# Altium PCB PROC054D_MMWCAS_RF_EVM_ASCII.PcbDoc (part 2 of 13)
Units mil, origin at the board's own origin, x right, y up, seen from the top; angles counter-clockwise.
Board outline 6299.21 x 5370.07 mil, 8 copper layers (L1 TOP, L2 GND, L3 SIGNAL 1, L4 GND, L5 SIGNAL 2, L6 SIGNAL 3, L7 GND, L8 BOTTOM), stack 53.5 mil thick; 775 components, 552 nets, 2648 pads, 7845 vias.
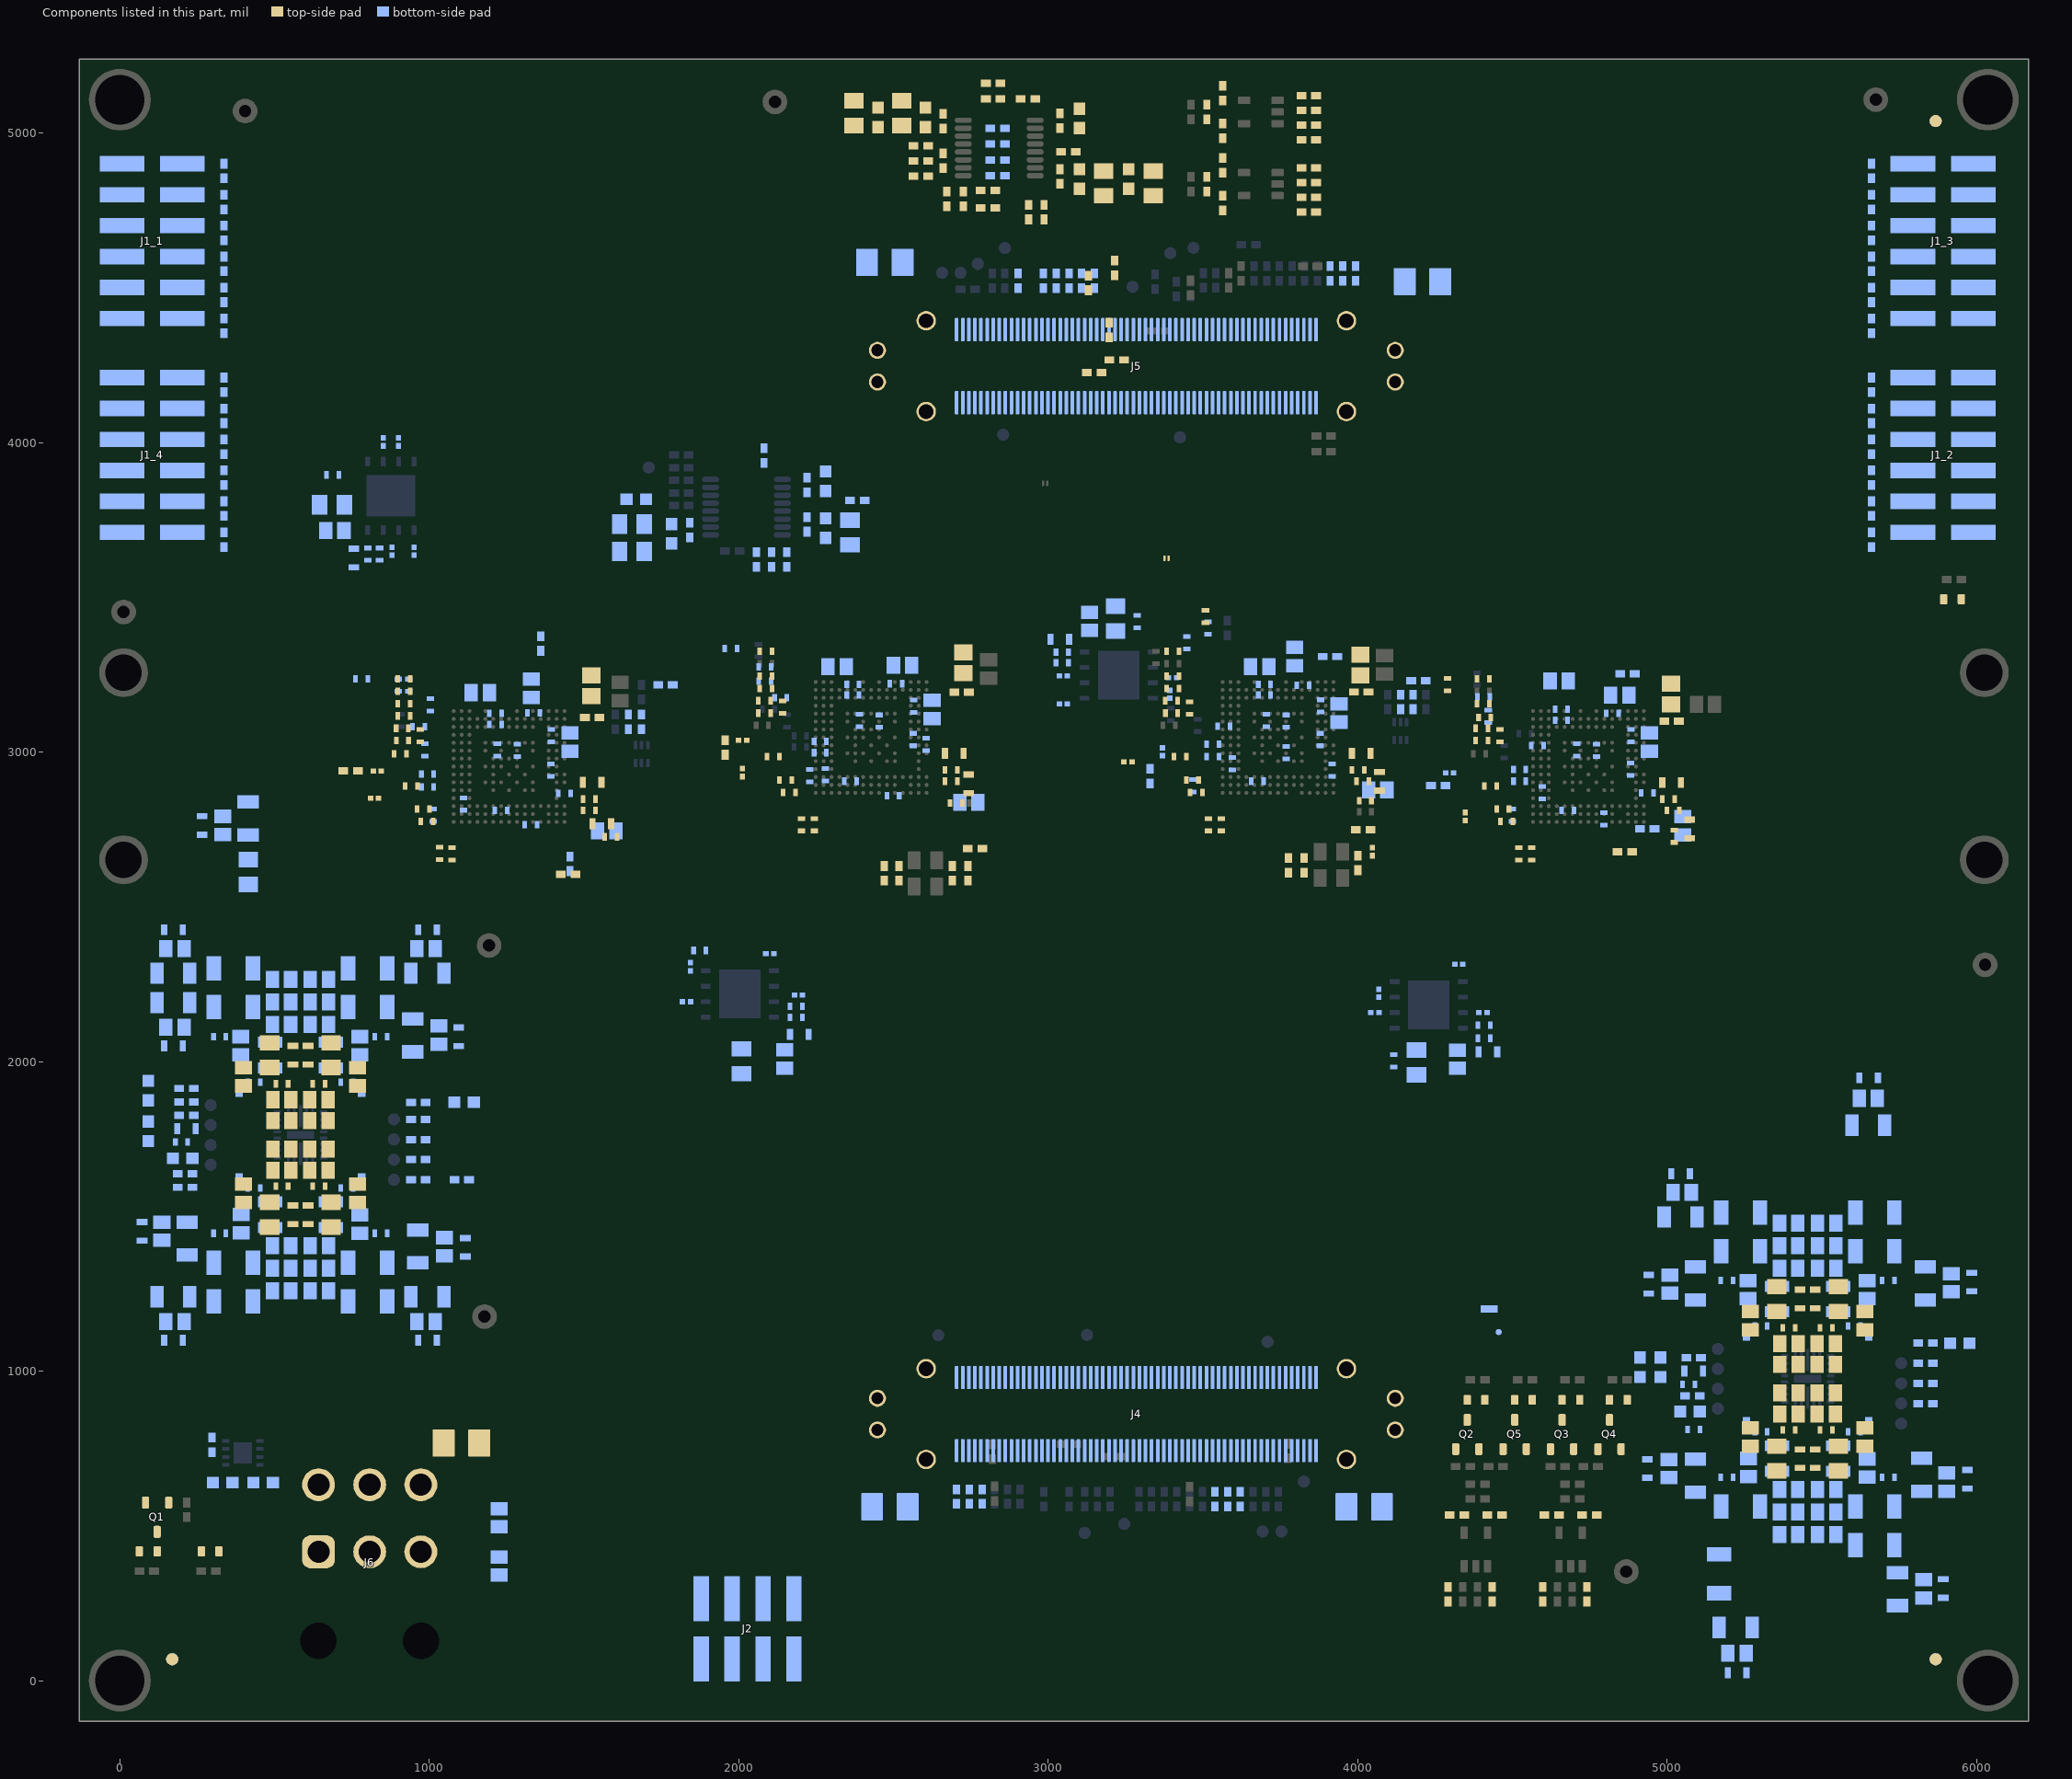
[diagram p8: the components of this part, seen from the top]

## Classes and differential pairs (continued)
net class "LC Power": AWR_1_1V0_RF1_FILT AWR_1_1V0_RF2_FILT AWR_1_1V2_FILT AWR_1_1V8_FILT AWR_2_1V0_RF1_FILT AWR_2_1V0_RF2_FILT AWR_2_1V2_FILT AWR_2_1V8_FILT AWR_3_1V0_RF1_FILT AWR_3_1V0_RF2_FILT AWR_3_1V2_FILT AWR_3_1V8_FILT AWR_4_1V0_RF1_FILT AWR_4_1V0_RF2_FILT AWR_4_1V2_FILT AWR_4_1V8_FILT
net class AWR_SYNC: AWR_1_DIG_SYNCIN AWR_1_DIG_SYNCIN_RS AWR_1_DIG_SYNCOUT AWR_2_DIG_SYNCIN AWR_2_DIG_SYNCIN_RS AWR_2_DIG_SYNCOUT AWR_3_DIG_SYNCIN AWR_3_DIG_SYNCIN_RS AWR_3_DIG_SYNCOUT AWR_4_DIG_SYNCIN AWR_4_DIG_SYNCIN_RS AWR_4_DIG_SYNCOUT DIG_SYNC_SOURCE DIG_SYNCOUT_RS_1 DIG_SYNCOUT_RS_2 DIG_SYNCOUT_RS_3 DIG_SYNCOUT_RS_4 EXT_DIG_SYNC
net class AWR_CLOCK: 40M_BUF_IN_PRIMAWRY 40M_BUF_IN_SECONDAWRY AWR_1_MCU_CLKOUT AWR_1_MCU_CLKOUT_CONN AWR_1_MCU_CLKOUT_RS AWR_1_OSC_CLKOUT AWR_1_OSC_CLKOUT_CONN AWR_1_PMIC_CLKOUT AWR_1_XTAL_CLKM AWR_1_XTAL_CLKP AWR_1_XTALP_RS AWR_2_MCU_CLKOUT AWR_2_OSC_CLKOUT AWR_2_PMIC_CLKOUT AWR_2_XTAL_CLKM AWR_2_XTAL_CLKP AWR_3_MCU_CLKOUT AWR_3_OSC_CLKOUT AWR_3_OSC_CLKOUT_CONN AWR_3_PMIC_CLKOUT AWR_3_XTAL_CLKM AWR_3_XTAL_CLKP AWR_3_XTALP_RS AWR_4_MCU_CLKOUT AWR_4_OSC_CLKOUT AWR_4_PMIC_CLKOUT AWR_4_XTAL_CLKM AWR_4_XTAL_CLKP BUF_CLKOUT1 BUF_CLKOUT1_RS BUF_CLKOUT2_RS BUF_CLKOUT3 BUF_CLKOUT3_RS BUF_CLKOUT4_RS EXT_40M_BUF_AWR_1_RS EXT_40MHZ_CLK_1V8 MCU_CLKOUT_RS_1 MCU_CLKOUT_RS_2 MCU_CLKOUT_RS_3 MCU_CLKOUT_RS_4 OSC_CLKOUT_RS_1 OSC_CLKOUT_RS_2 OSC_CLKOUT_RS_3 OSC_CLKOUT_RS_4 PMIC_CLKOUT_RS_1 PMIC_CLKOUT_RS_2 PMIC_CLKOUT_RS_3 PMIC_CLKOUT_RS_4
net class AWR_FMCW_20G: AWR_1_FMCW_CLKOUT AWR_1_FMCW_SYNCOUT AWR_2_FMCW_CLKOUT AWR_2_FMCW_SYNCOUT AWR_3_FMCW_CLKOUT AWR_3_FMCW_SYNCOUT AWR_4_FMCW_CLKOUT AWR_4_FMCW_SYNCOUT
net class 12XX_GENERAL: AWR_1_SPI_CLK1 AWR_1_SPI_CS1 AWR_1_SPI_HOST_INTR1 AWR_1_SPI_MISO1 AWR_1_SPI_MOSI1 AWR_2_SPI_CLK1 AWR_2_SPI_CS1 AWR_2_SPI_HOST_INTR1 AWR_2_SPI_MISO1 AWR_2_SPI_MOSI1 AWR_3_SPI_CLK1 AWR_3_SPI_CS1 AWR_3_SPI_HOST_INTR1 AWR_3_SPI_MISO1 AWR_3_SPI_MOSI1 AWR_4_SPI_CLK1 AWR_4_SPI_CS1 AWR_4_SPI_HOST_INTR1 AWR_4_SPI_MISO1 AWR_4_SPI_MOSI1 SPI_HOST_INTR1_RS_1 SPI_HOST_INTR1_RS_2 SPI_HOST_INTR1_RS_3 SPI_HOST_INTR1_RS_4 SPI_MISO1_RS_1 SPI_MISO1_RS_2 SPI_MISO1_RS_3 SPI_MISO1_RS_4
net class AWR_JTAG: AWR_1_TCK AWR_1_TDI AWR_1_TDO AWR_1_TMS AWR_2_TCK AWR_2_TDI AWR_2_TDO AWR_2_TMS AWR_3_TCK AWR_3_TDI AWR_3_TDO AWR_3_TMS AWR_4_TCK AWR_4_TDI AWR_4_TDO AWR_4_TMS TDO_RS_1 TDO_RS_2 TDO_RS_3 TDO_RS_4
net class "Back Drill Nets": AWR_1_FMCW_CLKOUT AWR_1_FMCW_SYNCOUT AWR_3_FMCW_CLKOUT
component class AWR_4: R174_4 R175_4 R176_4 R177_4 R178_4 R179_4 R180_4 R181_4 R182_4 R183_4 R184_4 R185_4
differential pair 12XX_4_LVDS_VALID: +AWR_4_LVDS_VALID_P -AWR_4_LVDS_VALID_N
differential pair 12XX_4_LVDS_FRCLK: +AWR_4_LVDS_FRCLK_P -AWR_4_LVDS_FRCLK_N
differential pair 12XX_4_CSI2_TX3: +AWR_4_CSI2_TX3_P -AWR_4_CSI2_TX3_N
differential pair 12XX_4_CSI2_TX2: +AWR_4_CSI2_TX2_P -AWR_4_CSI2_TX2_N
differential pair 12XX_4_CSI2_TX1: +AWR_4_CSI2_TX1_P -AWR_4_CSI2_TX1_N
differential pair 12XX_4_CSI2_TX0: +AWR_4_CSI2_TX0_P -AWR_4_CSI2_TX0_N
differential pair 12XX_4_CSI2_CLK: +AWR_4_CSI2_CLK_P -AWR_4_CSI2_CLK_N
differential pair 12XX_3_LVDS_VALID: +AWR_3_LVDS_VALID_P -AWR_3_LVDS_VALID_N
differential pair 12XX_3_LVDS_FRCLK: +AWR_3_LVDS_FRCLK_P -AWR_3_LVDS_FRCLK_N
differential pair 12XX_3_CSI2_TX3: +AWR_3_CSI2_TX3_P -AWR_3_CSI2_TX3_N
differential pair 12XX_3_CSI2_TX2: +AWR_3_CSI2_TX2_P -AWR_3_CSI2_TX2_N
differential pair 12XX_3_CSI2_TX1: +AWR_3_CSI2_TX1_P -AWR_3_CSI2_TX1_N
differential pair 12XX_3_CSI2_TX0: +AWR_3_CSI2_TX0_P -AWR_3_CSI2_TX0_N
differential pair 12XX_3_CSI2_CLK: +AWR_3_CSI2_CLK_P -AWR_3_CSI2_CLK_N
differential pair 12XX_2_LVDS_VALID: +AWR_2_LVDS_VALID_P -AWR_2_LVDS_VALID_N
differential pair 12XX_2_LVDS_FRCLK: +AWR_2_LVDS_FRCLK_P -AWR_2_LVDS_FRCLK_N
differential pair 12XX_2_CSI2_TX3: +AWR_2_CSI2_TX3_P -AWR_2_CSI2_TX3_N
differential pair 12XX_2_CSI2_TX2: +AWR_2_CSI2_TX2_P -AWR_2_CSI2_TX2_N
differential pair 12XX_2_CSI2_TX1: +AWR_2_CSI2_TX1_P -AWR_2_CSI2_TX1_N
differential pair 12XX_2_CSI2_TX0: +AWR_2_CSI2_TX0_P -AWR_2_CSI2_TX0_N
differential pair 12XX_2_CSI2_CLK: +AWR_2_CSI2_CLK_P -AWR_2_CSI2_CLK_N
differential pair 12XX_1_LVDS_VALID: +AWR_1_LVDS_VALID_P -AWR_1_LVDS_VALID_N
differential pair 12XX_1_LVDS_FRCLK: +AWR_1_LVDS_FRCLK_P -AWR_1_LVDS_FRCLK_N
differential pair 12XX_1_CSI2_TX3: +AWR_1_CSI2_TX3_P -AWR_1_CSI2_TX3_N
differential pair 12XX_1_CSI2_TX2: +AWR_1_CSI2_TX2_P -AWR_1_CSI2_TX2_N
differential pair 12XX_1_CSI2_TX1: +AWR_1_CSI2_TX1_P -AWR_1_CSI2_TX1_N
differential pair 12XX_1_CSI2_TX0: +AWR_1_CSI2_TX0_P -AWR_1_CSI2_TX0_N
differential pair " ": +AWR_1_CSI2_CLK_P -AWR_1_CSI2_CLK_N

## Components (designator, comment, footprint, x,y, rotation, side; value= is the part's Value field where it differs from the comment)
C1_1 "GCM188R71C105KA64D" 0603S 2742.78,2897.55 r90 top locked (schematic designator C1)
C1_2 "GCM188R71C105KA64D" 0603S 5073.3,2751.83 r270 top locked (schematic designator C1)
C1_3 "GCM188R71C105KA64D" 0603S 4070.8,2905.83 r90 top locked (schematic designator C1)
C1_4 "GCM188R71C105KA64D" 0603S 1557.76,2768.38 r0 top locked (schematic designator C1)
C2_1 "GCM155R71C224KE02D" 0402S 2563.59,3040.51 r90 bottom locked (schematic designator C2)
C2_2 "GCM155R71C224KE02D" 0402S 4881.59,2945.09 r90 bottom locked (schematic designator C2)
C2_3 "GCM155R71C224KE02D" 0402S 3878.59,3040.51 r90 bottom locked (schematic designator C2)
C2_4 "GCM155R71C224KE02D" 0402S 1393,2941.71 r90 bottom locked (schematic designator C2)
C3_1 "GCM188R71C105KA64D" 0603S 2696.55,2995.81 r0 top locked (schematic designator C3)
C3_2 "GCM188R71C105KA64D" 0603S 5014.55,2901.32 r0 top locked (schematic designator C3)
C3_3 "GCM188R71C105KA64D" 0603S 4011.55,2995.81 r0 top locked (schematic designator C3)
C3_4 "GCM188R71C105KA64D" 0603S 1526.55,2902.31 r0 top locked (schematic designator C3)
C4_1 "GCM155R71C224KE02D" 0402 2720.13,3194 r0 top locked (schematic designator C4)
C4_2 "GCM155R71C224KE02D" 0402 5014.43,3100.3 r0 top locked (schematic designator C4)
C4_3 "GCM155R71C224KE02D" 0402 4011.43,3194.3 r0 top locked (schematic designator C4)
C4_4 "GCM155R71C224KE02D" 0402 1526.43,3112.3 r0 top locked (schematic designator C4)
C5_1 "GCM21BR71A106KE22L" 0805 2725.58,3288.52 r90 top locked (schematic designator C5)
C5_2 "GCM21BR71A106KE22L" 0805 5012.4,3187.53 r90 top locked (schematic designator C5)
C5_3 "GCM21BR71A106KE22L" 0805 4008.9,3281.53 r90 top locked (schematic designator C5)
C5_4 "GCM21BR71A106KE22L" 0805 1523.9,3214.53 r90 top locked (schematic designator C5)
C6_1 "GCM21BR71A106KE22L" 0805L 2148.35,2008.07 r270 bottom locked (schematic designator C6)
C6_2 "GCM21BR71A106KE22L" 0805L 4322.67,2007.69 r270 bottom locked (schematic designator C6)
C6_3 "GCM21BR71A106KE22L" 0805L 3133.93,3422.47 r90 bottom locked (schematic designator C6)
C6_4 "GCM21BR71A106KE22L" 0805L 694.69,3715.83 r180 bottom locked (schematic designator C6)
C7_1 "GCM188R71C105KA64D" 0603S 2195.91,2087.69 r0 bottom locked (schematic designator C7)
C7_2 "GCM188R71C105KA64D" 0603S 4421.14,2031.28 r0 bottom locked (schematic designator C7)
C7_3 "GCM188R71C105KA64D" 0603S 3037.86,3364.87 r180 bottom locked (schematic designator C7)
C7_4 "GCM188R71C105KA64D" 0603S 756.26,3626.9 r270 bottom locked (schematic designator C7)
C8_1 "CGA2B3X7R1H104K050BB" 0402S 2185.91,2143.45 r0 bottom locked (schematic designator C8)
C8_2 "CGA2B3X7R1H104K050BB" 0402S 4408.64,2075.26 r0 bottom locked (schematic designator C8)
C8_3 "CGA2B3X7R1H104K050BB" 0402S 3045.36,3323.4 r180 bottom locked (schematic designator C8)
C8_4 "CGA2B3X7R1H104K050BB" 0402S 802,3639.4 r270 bottom locked (schematic designator C8)
C9 "GCM155R71C104KA55D" 0402 297.71,761.49 r90 bottom locked
C10 "GCM21BR71A106KE22L" 0805L 522.33,1259.8 r0 bottom locked
C11 "GCM31CR71A226KE02" 1206_180L 173.03,1240.08 r180 bottom locked
C12 "GCM21BR71A106KE22L" 0805L 178.04,1160.14 r180 bottom locked
C13 "GCM188R71C105KA64J" 0603S 173.04,1099.98 r180 bottom locked
C14 "GCM21BR71A106KE22L" 0805L 522.33,2193.13 r0 bottom locked
C15 "GCM31CR71A226KE02" 1206_180L 173.03,2190.59 r180 bottom locked
C16 "GCM21BR71A106KE22L" 0805L 178.04,2110.65 r180 bottom locked
C17 "GCM188R71C105KA64J" 0603S 173.04,2050.48 r180 bottom locked
C18 "GCM31CR71A226KE02" 1206_180L 414.55,2785.62 r90 bottom locked
C19 "GCM21BR71A106KE22L" 0805L 332.11,2762.78 r90 bottom locked
C20 "GCM188R71C105KA64J" 0603S 265.9,2763.05 r90 bottom locked
C21 "GCM31CR71A226KE02" 1206_180L 217.55,1428.37 r90 bottom locked
C22 "GCM31CR71A226KE02" 1206_180L 962.95,1403.1 r90 bottom locked
C23 "GCM21BR71A106KE22L" 0805L 1049.07,1401.66 r90 bottom locked
C24 "GCM31CR71A226KE02" 1206_180L 994.04,1240.08 r0 bottom locked
C25 "GCM21BR71A106KE22L" 0805L 644.75,1332.8 r180 bottom locked
C26 "GCM188R71C105KA64J" 0603S 1116.49,1399.97 r90 bottom locked
C27 "GCM21BR71A106KE22L" 0805L 644.75,1259.8 r180 bottom locked
C28 "GCM188R71C105KA64J" 0603S 994.03,1099.98 r0 bottom locked
C29 "GCM21BR71A106KE22L" 0805L 135.75,1452 r90 bottom locked
C30 "GCM31CR71A226KE02" 1206_180L 994.04,2285.85 r0 bottom locked
C31 "GCM21BR71A106KE22L" 0805L 989.03,2365.79 r0 bottom locked
C32 "GCM21BR71A106KE22L" 0805L 989.03,1160.14 r0 bottom locked
C33 "GCM21BR71A106KE22L" 0805L 644.75,2266.12 r180 bottom locked
C34 "GCM188R71C105KA64J" 0603S 994.03,2425.95 r0 bottom locked
C35 "GCM21BR71A106KE22L" 0805L 644.75,2193.13 r180 bottom locked
C36 "GCM188R71C105KA64J" 0603S 1095.23,2080.31 r270 bottom locked
C37 "GCM155R71H391KA37D" 0402S 733.8,1591.98 r0 bottom locked
C38 "GCM155R71H391KA37D" 0402S 433.28,1591.98 r180 bottom locked
C39 "GCM188R72A682KA37D" 0603S 608.24,1505.01 r90 top locked
C40 "GRM21BR60J107M" 0805L 643.44,1716.98 r180 top locked
C41 "GRM21BR60J107M" 0805L 768.09,1574.81 r90 top locked
C42 "GCM155R71C104JA55D" 0402S 643.45,1597.62 r180 top locked
C43 "GRM21BR71A106KA73L" 0805L 643.44,1648.99 r180 top locked
C44 "GCM188R72A682KA37D" 0603S 558.83,1505.01 r90 top locked
C45 "GRM21BR60J107M" 0805L 523.64,1716.98 r0 top locked
C46 "GRM21BR60J107M" 0805L 398.98,1574.81 r90 top locked
C47 "GCM155R71C104JA55D" 0402S 523.63,1597.62 r0 top locked
C48 "GRM21BR71A106KA73L" 0805L 523.64,1649.43 r0 top locked
C49 "GCM155R71H391KA37D" 0402S 733.8,1933.94 r0 bottom locked
C50 "GCM155R71H391KA37D" 0402S 433.28,1933.94 r180 bottom locked
C51 "GCM188R72A682KA37D" 0603S 608.24,2020.91 r270 top locked
C52 "GRM21BR60J107M" 0805L 643.44,1808.94 r180 top locked
C53 "GRM21BR60J107M" 0805L 768.09,1951.12 r270 top locked
C54 "GCM155R71C104JA55D" 0402S 643.45,1928.3 r180 top locked
C55 "GRM21BR71A106KA73L" 0805L 643.44,1876.94 r180 top locked
C56 "GCM188R72A682KA37D" 0603S 558.83,2020.91 r270 top locked
C57 "GRM21BR60J107M" 0805L 398.98,1951.12 r270 top locked
C58 "GRM21BR60J107M" 0805L 523.64,1808.94 r0 top locked
C59 "GCM155R71C104JA55D" 0402S 523.63,1928.3 r0 top locked
C60 "GRM21BR71A106KA73L" 0805L 523.64,1876.94 r0 top locked
C61 "C2012X7S1A226M125AC" 0805L 644.75,1405.79 r180 bottom locked
C62 "C2012X7S1A226M125AC" 0805L 775.98,1474.81 r90 bottom locked
C63 "GCM155R71C104JA55D" 0402S 199.53,1739.74 r180 bottom locked
C64 "C2012X7S1A226M125AC" 0805L 522.33,1405.79 r0 bottom locked
C65 "C2012X7S1A226M125AC" 0805L 392.43,1476.14 r90 bottom locked
C66 "C2012X7S1A226M125AC" 0805L 775.98,2051.12 r270 bottom locked
C67 "C2012X7S1A226M125AC" 0805L 644.75,2120.14 r180 bottom locked
C68 "C2012X7S1A226M125AC" 0805L 391.09,2051.12 r270 bottom locked
C69 "C2012X7S1A226M125AC" 0805L 522.33,2120.14 r0 bottom locked
C70 "GCM21BR71A106KE22L" 0805L 5393.06,544.94 r0 bottom locked
C71 "GCM31CR71A226KE02" 1206_180L 5091.14,662.09 r90 bottom locked
C72 "GCM21BR71A106KE22L" 0805L 5006.37,685.13 r90 bottom locked
C73 "GCM188R71C105KA64J" 0603S 4936.41,685.13 r90 bottom locked
C74 "GCM21BR71A106KE22L" 0805L 5393.06,1478.27 r0 bottom locked
C75 "GCM31CR71A226KE02" 1206_180L 5043.76,1497.99 r180 bottom locked
C76 "GCM21BR71A106KE22L" 0805L 5048.77,1577.93 r180 bottom locked
C77 "GCM188R71C105KA64J" 0603S 5043.77,1638.09 r180 bottom locked
C78 "GCM188R71C105KA64J" 0603S 71.91,1451.54 r90 bottom locked
C79 "GCM31CR71A226KE02" 1206_180L 5744.45,295.52 r270 bottom locked
C80 "GCM21BR71A106KE22L" 0805L 5829.19,296.85 r270 bottom locked
C81 "GCM31CR71A226KE02" 1206_180L 946.37,2084.69 r270 bottom locked
C82 "GCM21BR71A106KE22L" 0805L 5515.47,471.95 r180 bottom locked
C83 "GCM188R71C105KA64J" 0603S 5892.71,297.42 r270 bottom locked
C84 "GCM21BR71A106KE22L" 0805L 5515.47,544.94 r180 bottom locked
C85 "GCM188R71C105KA64J" 0603S 5970.63,650.66 r90 bottom locked
C86 "GCM21BR71A106KE22L" 0805L 522.33,2266.12 r0 bottom locked
C87 "GCM31CR71A226KE02" 1206_180L 5834.15,1283.42 r270 bottom locked
C88 "GCM21BR71A106KE22L" 0805L 5918.7,1285.61 r270 bottom locked
C89 "GCM21BR71A106KE22L" 0805L 1030.65,2085.79 r270 bottom locked
C90 "GCM21BR71A106KE22L" 0805L 5515.47,1405.27 r180 bottom locked
C91 "GCM188R71C105KA64J" 0603S 5984.53,1287.79 r270 bottom locked
C92 "GCM21BR71A106KE22L" 0805L 5515.47,1478.27 r180 bottom locked
C93 "GCM188R71C105KA64J" 0603S 5651.36,1947.85 r180 bottom locked
C94 "CGA2B3X7R1H104K050BB" 0402 3564.27,4896.25 r90 top locked
C95 "GCM155R71H391KA37D" 0402S 5604.52,804.13 r0 bottom locked
C96 "GCM155R71H391KA37D" 0402S 5304,804.13 r180 bottom locked
C97 "GCM188R72A682KA37D" 0603S 5429.56,1233.05 r270 top locked
C98 "GRM21BR60J107M" 0805L 5638.82,786.95 r90 top locked
C99 "GRM21BR60J107M" 0805L 5514.16,929.12 r180 top locked
C100 "GCM155R71C104JA55D" 0402S 5514.17,809.77 r180 top locked
C101 "GRM21BR71A106KA73L" 0805L 5514.16,861.13 r180 top locked
C102 "GCM188R72A682KA37D" 0603S 5478.97,717.16 r90 top locked
C103 "GRM21BR60J107M" 0805L 5269.71,786.95 r90 top locked
C104 "GRM21BR60J107M" 0805L 5394.36,929.12 r0 top locked
C105 "GCM155R71C104JA55D" 0402S 5394.35,809.77 r0 top locked
C106 "GRM21BR71A106KA73L" 0805L 5394.36,861.58 r0 top locked
C107 "GCM155R71H391KA37D" 0402S 5604.52,1146.09 r0 bottom locked
C108 "GCM155R71H391KA37D" 0402S 5304,1146.09 r180 bottom locked
C109 "GCM188R72A682KA37D" 0603S 5429.56,717.16 r90 top locked
C110 "GRM21BR60J107M" 0805L 5638.82,1163.26 r270 top locked
C111 "GRM21BR60J107M" 0805L 5514.16,1021.09 r180 top locked
C112 "GCM155R71C104JA55D" 0402S 5514.17,1140.45 r180 top locked
C113 "GRM21BR71A106KA73L" 0805L 5514.16,1089.08 r180 top locked
C114 "GCM188R72A682KA37D" 0603S 5478.97,1233.05 r270 top locked
C115 "GRM21BR60J107M" 0805L 5269.71,1163.26 r270 top locked
C116 "GRM21BR60J107M" 0805L 5394.36,1021.09 r0 top locked
C117 "GCM155R71C104JA55D" 0402S 5394.35,1140.45 r0 top locked
C118 "GRM21BR71A106KA73L" 0805L 5394.36,1089.08 r0 top locked
C119 "C2012X7S1A226M125AC" 0805L 5515.47,617.93 r180 bottom locked
C120 "C2012X7S1A226M125AC" 0805L 5646.71,686.95 r90 bottom locked
C121 "GCM155R71C104JA55D" 0402S 5070.26,956.89 r180 bottom locked
C122 "C2012X7S1A226M125AC" 0805L 5393.06,617.93 r0 bottom locked
C123 "C2012X7S1A226M125AC" 0805L 5263.16,688.29 r90 bottom locked
C124 "C2012X7S1A226M125AC" 0805L 5646.71,1263.26 r270 bottom locked
C125 "C2012X7S1A226M125AC" 0805L 5515.47,1332.28 r180 bottom locked
C126 "C2012X7S1A226M125AC" 0805L 5261.82,1263.26 r270 bottom locked
C127 "C2012X7S1A226M125AC" 0805L 5393.06,1332.28 r0 bottom locked
C128_1 "GCM155R71C224KE02D" 0402S 2507.72,3221.01 r0 bottom locked (schematic designator C128)
C128_2 "GCM155R71C224KE02D" 0402S 4823.23,3125.03 r0 bottom locked (schematic designator C128)
C128_3 "GCM155R71C224KE02D" 0402S 3704.89,3101.69 r270 bottom locked (schematic designator C128)
C128_4 "GCM155R71C224KE02D" 0402S 1337.72,3127.01 r0 bottom locked (schematic designator C128)
C129_1 "GCM155R71C224KE02D" 0402S 2389.89,3101.69 r270 bottom locked (schematic designator C129)
C129_2 "GCM155R71C224KE02D" 0402S 4707.89,3007.69 r270 bottom locked (schematic designator C129)
C129_3 "GCM155R71C224KE02D" 0402S 3822.72,3216.01 r0 bottom locked (schematic designator C129)
C129_4 "GCM155R71C224KE02D" 0402S 1219.89,3007.69 r270 bottom locked (schematic designator C129)
C130_1 "GCM21BR71A106KE22L" 0805L 2529.43,3280.8 r0 bottom locked (schematic designator C130)
C130_2 "GCM21BR71A106KE22L" 0805L 4847.43,3183.8 r0 bottom locked (schematic designator C130)
C130_3 "GCM21BR71A106KE22L" 0805L 3796.42,3308.91 r90 bottom locked (schematic designator C130)
C130_4 "GCM21BR71A106KE22L" 0805L 1329.9,3206.33 r90 bottom locked (schematic designator C130)
C131_1 "GCM155R71C224KE02D" 0402S 2686.84,2942.02 r0 top locked (schematic designator C131)
C131_2 "GCM155R71C224KE02D" 0402S 5004.84,2848.02 r0 top locked (schematic designator C131)
C131_3 "GCM155R71C224KE02D" 0402S 4016.84,2906.06 r0 top locked (schematic designator C131)
C131_4 "GCM155R71C224KE02D" 0402S 1516.84,2848.02 r0 top locked (schematic designator C131)
C132_1 "GCM155R71C224KE02D" 0402S 2686.84,2906.06 r0 top locked (schematic designator C132)
C132_2 "GCM155R71C224KE02D" 0402S 5019.84,2812.06 r0 top locked (schematic designator C132)
C132_3 "GCM155R71C224KE02D" 0402S 4001.84,2942.02 r0 top locked (schematic designator C132)
C132_4 "GCM155R71C224KE02D" 0402S 1516.84,2812.06 r0 top locked (schematic designator C132)
C133_1 "GCM21BR71A106KE22L" 0805L 2743.75,2837.89 r0 bottom locked (schematic designator C133)
C133_2 "GCM21BR71A106KE22L" 0805L 5050.19,2762.16 r270 bottom locked (schematic designator C133)
C133_3 "GCM21BR71A106KE22L" 0805L 4065.03,2878.26 r0 bottom locked (schematic designator C133)
C133_4 "GCM21BR71A106KE22L" 0805L 1573.1,2745.99 r0 bottom locked (schematic designator C133)
C134_1 "GCM155R71C224KE02D" 0402S 2605.98,3025.49 r90 bottom locked (schematic designator C134)
C134_2 "GCM155R71C224KE02D" 0402S 4936.09,2868 r0 bottom locked (schematic designator C134)
C134_3 "GCM155R71C224KE02D" 0402S 3918.09,2942 r270 bottom locked (schematic designator C134)
C134_4 "GCM155R71C224KE02D" 0402S 1437.23,2867 r0 bottom locked (schematic designator C134)
C135_1 "GCM155R71C224KE02D" 0402S 2361.3,2906 r180 bottom locked (schematic designator C135)
C135_2 "GCM155R71C224KE02D" 0402S 4679.3,2812 r180 bottom locked (schematic designator C135)
C135_3 "GCM155R71C224KE02D" 0402S 3676.3,2906 r180 bottom locked (schematic designator C135)
C135_4 "GCM155R71C224KE02D" 0402S 1231.3,2812 r0 bottom locked (schematic designator C135)
C136_1 "GCM155R71C224KE02D" 0402S 2454.38,3100.07 r270 bottom locked (schematic designator C136)
C136_2 "GCM155R71C224KE02D" 0402S 4772.38,3006.07 r270 bottom locked (schematic designator C136)
C136_3 "GCM155R71C224KE02D" 0402S 3769.38,3100.07 r270 bottom locked (schematic designator C136)
C136_4 "GCM155R71C224KE02D" 0402S 1284.38,3006.07 r270 bottom locked (schematic designator C136)
C137_1 "GCM155R71C224KE02D" 0402S 2369.09,3184.18 r180 bottom locked (schematic designator C137)
C137_2 "GCM155R71C224KE02D" 0402S 4659,3103.53 r180 bottom locked (schematic designator C137)
C137_3 "GCM155R71C224KE02D" 0402S 3699.09,3218.8 r180 bottom locked (schematic designator C137)
C137_4 "GCM155R71C224KE02D" 0402S 1214.09,3090.18 r180 bottom locked (schematic designator C137)
C138_1 "GCM155R71C224KE02D" 0402S 2369.09,3218.8 r180 bottom locked (schematic designator C138)
C138_2 "GCM155R71C224KE02D" 0402S 4659,3138.15 r180 bottom locked (schematic designator C138)
C138_3 "GCM155R71C224KE02D" 0402S 3699.09,3184.18 r180 bottom locked (schematic designator C138)
C138_4 "GCM155R71C224KE02D" 0402S 1214.09,3124.8 r180 bottom locked (schematic designator C138)
C139_1 "GCM21BR71A106KE22L" 0805L 2318.38,3275.59 r180 bottom locked (schematic designator C139)
C139_2 "GCM21BR71A106KE22L" 0805L 4651.52,3229.77 r180 bottom locked (schematic designator C139)
C139_3 "GCM21BR71A106KE22L" 0805L 3683.72,3276.04 r180 bottom locked (schematic designator C139)
C139_4 "GCM21BR71A106KE22L" 0805L 1164.56,3192.04 r180 bottom locked (schematic designator C139)
C140_1 "GCM155R71C224KE02D" 0402S 2564.98,3147.69 r270 bottom locked (schematic designator C140)
C140_2 "GCM155R71C224KE02D" 0402S 4882.98,3053.69 r270 bottom locked (schematic designator C140)
C140_3 "GCM155R71C224KE02D" 0402S 3879.98,3149.11 r270 bottom locked (schematic designator C140)
C140_4 "GCM155R71C224KE02D" 0402S 1394.98,3053.69 r270 bottom locked (schematic designator C140)
C141_1 "GCM21BR71A106KE22L" 0805L 2624.84,3138.16 r270 bottom locked (schematic designator C141)
C141_2 "GCM21BR71A106KE22L" 0805L 4942.98,3032.5 r270 bottom locked (schematic designator C141)
C141_3 "GCM21BR71A106KE22L" 0805L 3939.98,3126.5 r270 bottom locked (schematic designator C141)
C141_4 "GCM21BR71A106KE22L" 0805L 1454.98,3032.5 r270 bottom locked (schematic designator C141)
C142_1 "GCM155R71C224KE02D" 0402S 2141.49,3145.71 r90 top locked (schematic designator C142)
C142_2 "GCM155R71C224KE02D" 0402S 4562,2671.58 r270 top locked (schematic designator C142)
C142_3 "GCM155R71C224KE02D" 0402S 3457.49,3142.71 r90 top locked (schematic designator C142)
C142_4 "GCM155R71C224KE02D" 0402S 971.49,3053.71 r90 top locked (schematic designator C142)
C143_1 "GCM155R71C224KE02D" 0402S 2244,2765.58 r270 top locked (schematic designator C143)
C143_2 "GCM155R71C224KE02D" 0402S 4459.99,3053.71 r90 top locked (schematic designator C143)
C143_3 "GCM155R71C224KE02D" 0402S 3559,2765.58 r270 top locked (schematic designator C143)
C143_4 "GCM155R71C224KE02D" 0402S 1074,2671.58 r270 top locked (schematic designator C143)
C144_1 "GCM155R71C224KE02D" 0402S 2498.51,2859.53 r0 bottom locked (schematic designator C144)
C144_2 "GCM155R71C224KE02D" 0402S 4596.3,2868.9 r270 bottom locked (schematic designator C144)
C144_3 "GCM155R71C224KE02D" 0402S 3769.06,2998.27 r90 bottom locked (schematic designator C144)
C144_4 "GCM155R71C224KE02D" 0402S 1110.64,2832.35 r270 bottom locked (schematic designator C144)
C145_1 "GCM155R71C224KE02D" 0402S 2280.64,2926.35 r270 bottom locked (schematic designator C145)
C145_2 "GCM155R71C224KE02D" 0402S 4796.51,2783.84 r270 bottom locked (schematic designator C145)
C145_3 "GCM155R71C224KE02D" 0402S 3595.75,2962.9 r270 bottom locked (schematic designator C145)
C145_4 "GCM155R71C224KE02D" 0402S 1328.51,2765.53 r0 bottom locked (schematic designator C145)
C146_1 "GCM155R71C104KA55D" 0402S 2163.58,2870 r180 top locked (schematic designator C146)
C146_2 "GCM155R71C104KA55D" 0402S 4481.58,2776 r180 top locked (schematic designator C146)
C146_3 "GCM155R71C104KA55D" 0402S 3478.58,2870 r180 top locked (schematic designator C146)
C146_4 "GCM155R71C104KA55D" 0402S 992.8,2776 r180 top locked (schematic designator C146)
C147_1 "GCM155R71C104KA55D" 0402S 2203,2765.58 r270 top locked (schematic designator C147)
C147_2 "GCM155R71C104KA55D" 0402S 4521,2671.58 r270 top locked (schematic designator C147)
C147_3 "GCM155R71C104KA55D" 0402S 3518,2765.58 r270 top locked (schematic designator C147)
C147_4 "GCM155R71C104KA55D" 0402S 1033,2673 r270 top locked (schematic designator C147)
C148_1 "GCM155R71C224KE02D" 0402S 2229,2924.28 r270 bottom locked (schematic designator C148)
C148_2 "GCM155R71C224KE02D" 0402S 4500,2795.58 r270 bottom locked (schematic designator C148)
C148_3 "GCM155R71C224KE02D" 0402S 3466.95,2891 r270 bottom locked (schematic designator C148)
C148_4 "GCM155R71C224KE02D" 0402S 1012,2795.58 r270 bottom locked (schematic designator C148)
C149 "CGA2B3X7R1H104K050BB" 0402 3564.27,5129.3 r90 top locked
C150 "GCM31CR71A226KE02" 1206_180L 173.03,2285.84 r180 bottom locked
C151 "GCM21BR71A106KE22L" 0805L 178.04,2365.78 r180 bottom locked
C152 "GCM188R71C105KA64J" 0603S 173.04,2425.94 r180 bottom locked
C153 "GCM21BR71A106KE22L" 0805L 5393.06,471.95 r0 bottom locked
C154 "GCM31CR71A226KE02" 1206_180L 5221.38,171.94 r0 bottom locked
C155 "GCM21BR71A106KE22L" 0805L 5226.35,89.14 r0 bottom locked
C156 "GCM188R71C105KA64J" 0603S 5226.35,25.17 r0 bottom locked
C157 "GCM21BR71A106KE22L" 0805L 5393.06,1405.27 r0 bottom locked
C158 "GCM31CR71A226KE02" 1206_180L 5091.39,1283.32 r270 bottom locked
C159 "GCM21BR71A106KE22L" 0805L 5009.39,1281.05 r270 bottom locked
C160 "GCM188R71C105KA64J" 0603S 4940.6,1280.76 r270 bottom locked
C161 "GCM21BR71A106KE22L" 0805L 522.33,1332.8 r0 bottom locked
C162 "GCM155R71C104KA55D" 0402 4320.97,535.63 r180 top locked
C163 "GCM155R71C104KA55D" 0402 4627.42,535.63 r180 top locked
C164 "GCM155R71C104KA55D" 0402 3564.27,4774.2 r270 top locked
C165 "GCM155R71C104KA55D" 0402 3564.27,5007.25 r270 top locked
C166 "GCM31CR71A226KE02" 1206_180L 5822.48,664.93 r90 bottom locked
C167 "GJM1555C1H4R7BB01D" 0402 2690.4,2608.27 r90 top locked
C168 "GJM1555C1H4R7BB01D" 0402 2518.3,2608.27 r90 top locked
C169 "GCM21BR71A106KE22L" 0805_HV 2372.39,5064.49 r270 top locked
C170 "GCM155R71C224KE02D" 0402 2660.57,5038.49 r90 top locked
C171 "GCM188R70J225KE22D" 0603 2603.2,5050.47 r270 top locked
C172 "GCM21BR71A106KE22L" 0805_HV 2526.41,5064.49 r90 top locked
C173 "GJM1555C1H4R7BB01D" 0402 4001.11,2642 r90 top locked
C174 "GJM1555C1H4R7BB01D" 0402 3826.93,2634.28 r270 top locked
C175 "GCM21BR71A106KE22L" 0805_HV 3339.25,4837.72 r90 top locked
C176 "GCM21BR71A106KE22L" 0805_HV 3178.88,4837.72 r270 top locked
C177 "GCM155R71C224KE02D" 0402 3038.3,4859.61 r270 top locked
C178 "GCM188R70J225KE22D" 0603 3100.57,5047.4 r270 top locked
C179 "GCM155R71C224KE02D" 0402 3038.3,5039.53 r90 top locked
C180 "GCM188R70J225KE22D" 0603 3100.57,4851.73 r90 top locked
C181 "GCM21BR71A106KE22L" 0805_HV 1655.02,3648.2 r180 bottom locked
C182 "GCM155R71C224KE02D" 0402 1841.77,3717.5 r270 bottom locked
C183 "GCM188R70J225KE22D" 0603 1783.09,3705.52 r90 bottom locked
C184 "GCM21BR71A106KE22L" 0805_HV 1655.02,3737.01 r180 bottom locked
C185 "GCM21BR71A106KE22L" 0805_HV 2359.46,3709.7 r90 bottom locked
C186 "GCM155R71C224KE02D" 0402 2220.98,3735.85 r90 bottom locked
C187 "GCM188R70J225KE22D" 0603 2280.22,3723.87 r270 bottom locked
C188 "GCM155R71C224KE02D" 0402 2220.98,3863.05 r90 bottom locked
C189 "GCM188R70J225KE22D" 0603 2280.22,3875.03 r270 bottom locked
C190 "T491B476K010AT" 3528-21 4021.54,561.82 r0 bottom locked
C191 "T491B476K010AT" 3528-21 2488.3,561.82 r180 bottom locked
C192 "T491B476K010AT" 3528-21 2472.09,4582.18 r180 bottom
C193 "T491B476K010AT" 3528-21 4209.7,4520.2 r0 bottom
C194 "T491B476K010AT" 3528-21 1103.88,767.73 r0 top locked
C195 "C0402C103K4RACTU" 0402 1686.31,3097.83 r90 bottom locked
C196 "CGA2B3X7R1H104K050BB" 0402 1643.31,3097.84 r90 bottom locked
C197 "CGA2B3X7R1H104K050BB" 0402 1762.95,3217.44 r0 bottom locked
C198 "CGA2B3X7R1H104K050BB" 0402 4196.84,3230.71 r180 bottom locked
C199 "C0402C103K4RACTU" 0402 4138.47,3162.21 r90 bottom locked
C200 "CGA2B3X7R1H104K050BB" 0402 4179.47,3162.21 r90 bottom locked
C201 "GCM21BR71A106KE22L" 0805L 5904.25,641.77 r90 bottom locked
C202 "GCM188R71C105KA64J" 0603 463.3,640.08 r180 bottom locked
C203 "GCM188R71C105KA64J" 0603 332.14,640.15 r0 bottom locked
C204 "GCM31CR71A226KE02" 1206_180L 5650.52,1794.57 r180 bottom locked
C205 "CGA2B3X7R1H104K050BB" 0402 4443.02,535.63 r0 top locked
C206 "CGA2B3X7R1H104K050BB" 0402 4749.46,535.63 r0 top locked
C207 "GCM21BR71A106KE22L" 0805L 5650.43,1881.43 r180 bottom locked
DS1 "TLMS1000-GS08" TLMx1000_Red 291.9,417.61 r0 top locked
DS2 "TLMS1000-GS08" TLMx1000_Red 5922.6,3493.76 r180 top locked
DS3 "TLMY1000-GS08" TLMx1000_Yellow 91.9,417.61 r0 top locked
DS4 "TLMY1000-GS08" TLMx1000_Yellow 4382.93,906.78 r180 top locked
DS5 "TLMY1000-GS08" TLMx1000_Yellow 4689.38,906.78 r180 top locked
DS6 "TLMY1000-GS08" TLMx1000_Yellow 4842.6,906.78 r180 top locked
DS7 "TLMY1000-GS08" TLMx1000_Yellow 4536.15,906.78 r180 top locked
FID1 "Fiducial" Fiducial10-20 5868,5039 r90 top locked
FID2 "Fiducial" Fiducial10-20 169,69 r90 top locked
FID3 "Fiducial" Fiducial10-20 5868,69 r90 top locked
FID4 "Fiducial" Fiducial10-20 169,69 r90 bottom locked
FID5 "Fiducial" Fiducial10-20 5868,69 r90 bottom locked
FID6 "Fiducial" Fiducial10-20 5868,5039 r90 bottom locked
J1_1 "TSM-106-01-L-DV" Samtec_TSM-106-01-x-DV 104.76,4650.95 r180 bottom locked (schematic designator J1)
J1_2 "TSM-106-01-L-DV" Samtec_TSM-106-01-x-DV 5892.24,3960.13 r0 bottom locked (schematic designator J1)
J1_3 "TSM-106-01-L-DV" Samtec_TSM-106-01-x-DV 5892.24,4650.95 r0 bottom locked (schematic designator J1)
J1_4 "TSM-106-01-L-DV" Samtec_TSM-106-01-x-DV 104.76,3960.13 r180 bottom locked (schematic designator J1)
J2 "TSM-104-01-L-DV" Samtec_TSM-104-01-x-DV 2028.45,167.06 r270 bottom locked
J3 "19S101-40ML5" 19S101_40ML5 4534.87,1201.17 r90 bottom locked
J4 "FX23-120P-0.5SV15" Hirose_FX23-120P-0_5SV15 3284.92,861.13 r270 bottom locked
J5 "FX23-120P-0.5SV15" Hirose_FX23-120P-0_5SV15 3284.92,4246.95 r270 bottom locked
J6 "0039300060" Molex_0039300060 807.36,128.84 r270 bottom locked
L1 "NLCV32T-R10M-EFRD" NLCV32 366.61,1225.32 r180 bottom locked
L2 "NLCV32T-R10M-EFRD" NLCV32 366.61,2175.82 r180 bottom locked
L3 "NLCV32T-R10M-EFRD" NLCV32 366.61,1350.1 r180 bottom locked
L4 "NLCV32T-R10M-EFRD" NLCV32 800.47,1350.1 r0 bottom locked
L5 "NLCV32T-R10M-EFRD" NLCV32 800.47,1225.32 r0 bottom locked
L6 "NLCV32T-R10M-EFRD" NLCV32 366.61,2300.61 r180 bottom locked
L7 "NLCV32T-R10M-EFRD" NLCV32 800.47,2300.61 r0 bottom locked
L8 "NLCV32T-R10M-EFRD" NLCV32 800.47,2175.82 r0 bottom locked
L9 "BLM21PG300SH1D" 0805_HV 682.81,1505.28 r90 top locked
L10 "BLM21PG300SH1D" 0805_HV 484.26,1505.28 r90 top locked
L11 "BLM21PG300SH1D" 0805_HV 682.81,2020.65 r270 top locked
L12 "BLM21PG300SH1D" 0805_HV 484.26,2020.65 r270 top locked
L13 "DFE252012PD-R47M" DFE252012P 681.93,1505.16 r270 bottom locked
L14 "DFE252012PD-R47M" DFE252012P 485.15,1505.16 r270 bottom locked
L15 "DFE252012PD-R47M" DFE252012P 681.93,2020.76 r90 bottom locked
L16 "DFE252012PD-R47M" DFE252012P 485.15,2020.76 r90 bottom locked
L17 "NLCV32T-R10M-EFRD" NLCV32 5237.33,562.25 r180 bottom locked
L18 "NLCV32T-R10M-EFRD" NLCV32 5237.33,1512.75 r180 bottom locked
L19 "NLCV32T-R10M-EFRD" NLCV32 5168.15,344.97 r270 bottom locked
L20 "NLCV32T-R10M-EFRD" NLCV32 5671.19,437.46 r0 bottom locked
L21 "NLCV32T-R10M-EFRD" NLCV32 5671.19,562.25 r0 bottom locked
L22 "NLCV32T-R10M-EFRD" NLCV32 5237.33,1387.96 r180 bottom locked
L23 "NLCV32T-R10M-EFRD" NLCV32 5671.19,1387.96 r0 bottom locked
L24 "NLCV32T-R10M-EFRD" NLCV32 5671.19,1512.75 r0 bottom locked
L25 "BLM21PG300SH1D" 0805_HV 5553.54,717.42 r90 top locked
L26 "BLM21PG300SH1D" 0805_HV 5354.99,717.42 r90 top locked
L27 "BLM21PG300SH1D" 0805_HV 5553.54,1232.79 r270 top locked
L28 "BLM21PG300SH1D" 0805_HV 5354.99,1232.79 r270 top locked
L29 "DFE252012PD-R47M" DFE252012P 5552.65,717.3 r270 bottom locked
L30 "DFE252012PD-R47M" DFE252012P 5355.87,717.3 r270 bottom locked
L31 "DFE252012PD-R47M" DFE252012P 5552.65,1232.91 r90 bottom locked
L32 "DFE252012PD-R47M" DFE252012P 5355.87,1232.91 r90 bottom locked
L33 "BLM18SG121TN1D" 0603 2450.31,5050.47 r270 top locked
L34 "BLM18SG121TN1D" 0603 3260.01,4851.73 r90 top locked
L35 "BLM18SG121TN1D" 0603 1669.04,3816.87 r0 bottom locked
Logo1 "CE MAWRk" CE_Mark_5mm 5859.14,4655.58 r0 top locked
Logo2 "Texas Instruments" TI_Stacked_Overlay_Small 3704.87,99.62 r0 top locked
Logo3 "FCC disclaimer" FCC_disclaimer 4988.06,6271.78 r0 top locked
Logo4 "WEEE logo" WEEE_Minimum 5859.14,4323.69 r0 top locked
Logo5 "ESD Susceptible" ESD_Overlay_Large 1902.61,792.81 r0 top locked
LOGO6 "CAUTION HOT SURFACE" IEC_HotSurface_Large 5623.06,1848.13 r0 top locked
Q1 "BSS123" SOT-23 120.44,527.89 r270 top locked
Q2 "BSS123" SOT-23 4354.39,795.2 r90 top locked
Q3 "BSS123" SOT-23 4660.83,795.2 r90 top locked
Q4 "BSS123" SOT-23 4814.06,795.2 r90 top locked
Q5 "BSS123" SOT-23 4507.61,795.2 r90 top locked
R1_1 "CRCW040233R2FKED" 0402S 2111.9,2985 r0 top locked (schematic designator R1)
R1_2 "CRCW040233R2FKED" 0402S 4429.9,2891 r0 top locked (schematic designator R1)
R1_3 "CRCW040233R2FKED" 0402S 3426.9,2985 r0 top locked (schematic designator R1)
R1_4 "CRCW040233R2FKED" 0402S 941.9,2891 r0 top locked (schematic designator R1)
R2_1 "CRCW040233R2FKED" 0402S 2702.88,2834.89 r180 top locked (schematic designator R2)
R2_2 "CRCW040233R2FKED" 0402S 5022.77,2728.4 r90 top locked (schematic designator R2)
R2_3 "CRCW040233R2FKED" 0402S 4024.71,2842.4 r180 top locked (schematic designator R2)
R2_4 "CRCW040233R2FKED" 0402S 1587.14,2726.23 r180 top locked (schematic designator R2)
R3_1 "CRCW040247K5FKED" 0402 1955.47,3015.03 r270 top locked (schematic designator R3)
R3_2 "CRCW040247K5FKED" 0402 4260.87,2891.34 r180 bottom locked (schematic designator R3)
R3_3 "CRCW040247K5FKED" 0402 3328.84,2922.71 r270 bottom locked (schematic designator R3)
R3_4 "CRCW040247K5FKED" 0402 745.96,2938.96 r180 top locked (schematic designator R3)
R4_1 "CRCW040233R2FKED" 0402S 2151,2910 r0 top locked (schematic designator R4)
R4_2 "CRCW040233R2FKED" 0402S 4469,2816 r0 top locked (schematic designator R4)
R4_3 "CRCW040233R2FKED" 0402S 3466,2910 r0 top locked (schematic designator R4)
R4_4 "CRCW040233R2FKED" 0402S 981,2816 r0 top locked (schematic designator R4)
R5_1 "CRCW040233R2FKED" 0402S 2263.7,3034.15 r0 bottom locked (schematic designator R5)
R5_2 "CRCW040233R2FKED" 0402S 4523.9,2943.53 r0 bottom locked (schematic designator R5)
R5_3 "CRCW040233R2FKED" 0402S 3531.46,3026.2 r0 bottom locked (schematic designator R5)
R5_4 "CRCW040233R2FKED" 0402S 994.55,2928.78 r0 bottom locked (schematic designator R5)
R6_1 "CRCW02010000Z0ED" 0201 2012.51,3038.66 r180 top locked (schematic designator R6)
R6_2 "CRCW02010000Z0ED" 0201 4297.49,2932.79 r180 bottom locked (schematic designator R6)
R6_3 "CRCW02010000Z0ED" 0201 3369.29,3001.01 r270 bottom locked (schematic designator R6)
R6_4 "CRCW02010000Z0ED" 0201 831.79,2938.96 r180 top locked (schematic designator R6)
R7_1 "CRCW02010000Z0ED" 0201 2012.41,2934.01 r270 top locked (schematic designator R7)
R7_2 "CRCW02010000Z0ED" 0201 4347.63,2791.93 r270 top locked (schematic designator R7)
R7_3 "CRCW02010000Z0ED" 0201 3258.01,2969 r180 top locked (schematic designator R7)
R7_4 "CRCW02010000Z0ED" 0201 823.23,2851.34 r180 top locked (schematic designator R7)
R8_1 "CRCW040233R2FKED" 0402S 2263.7,2998.15 r180 bottom locked (schematic designator R8)
R8_2 "CRCW040233R2FKED" 0402S 4523.9,2906 r180 bottom locked (schematic designator R8)
R8_3 "CRCW040233R2FKED" 0402S 3531.46,2985.2 r180 bottom locked (schematic designator R8)
R8_4 "CRCW040233R2FKED" 0402S 994.55,2887.78 r180 bottom locked (schematic designator R8)
R9_1 "ERJ-2GE0R00X" 0402S 2135.9,3176 r0 bottom locked (schematic designator R9)
R9_2 "ERJ-2GE0R00X" 0402S 4580.6,3020.95 r0 bottom locked (schematic designator R9)
R9_3 "ERJ-2GE0R00X" 0402S 3567.22,3084.16 r0 bottom locked (schematic designator R9)
R9_4 "ERJ-2GE0R00X" 0402S 965.9,3082 r0 bottom locked (schematic designator R9)
R10_1 "CRCW040233R2FKED" 0402S 2083,3126 r180 top locked (schematic designator R10)
R10_2 "CRCW040233R2FKED" 0402S 4400.91,3037 r180 top locked (schematic designator R10)
R10_3 "CRCW040233R2FKED" 0402S 3398.91,3126 r180 top locked (schematic designator R10)
R10_4 "CRCW040233R2FKED" 0402S 913,3037 r180 top locked (schematic designator R10)
R11_1 "CRCW040233R2FKED" 0402S 2084.31,3229 r0 bottom locked (schematic designator R11)
R11_2 "CRCW040233R2FKED" 0402S 4422.06,3115 r90 bottom locked (schematic designator R11)
R11_3 "CRCW040233R2FKED" 0402S 3516,3400.34 r270 bottom locked (schematic designator R11)
R11_4 "CRCW040233R2FKED" 0402S 1003.91,3152.94 r270 bottom (schematic designator R11)
R12_1 "CRCW040233R2FKED" 0402S 2083,3166 r180 top locked (schematic designator R12)
R12_2 "CRCW040233R2FKED" 0402S 4400.89,3077 r180 top locked (schematic designator R12)
R12_3 "CRCW040233R2FKED" 0402S 3398.89,3166 r180 top locked (schematic designator R12)
R12_4 "CRCW040233R2FKED" 0402S 912.89,3077 r180 top locked (schematic designator R12)
R13_1 "CRCW040233R2FKED" 0402S 2088,3326 r0 top locked (schematic designator R13)
R13_2 "CRCW040233R2FKED" 0402S 4405.9,3237 r0 top locked (schematic designator R13)
R13_3 "CRCW040233R2FKED" 0402S 3402.9,3326 r0 top locked (schematic designator R13)
R13_4 "CRCW040233R2FKED" 0402S 917.9,3237 r0 top locked (schematic designator R13)
R14_1 "CRCW040233R2FKED" 0402S 2088,3246 r0 top locked (schematic designator R14)
R14_2 "CRCW040233R2FKED" 0402S 4405.89,3157 r0 top locked (schematic designator R14)
R14_3 "CRCW040233R2FKED" 0402S 3402.89,3246 r0 top locked (schematic designator R14)
R14_4 "CRCW040233R2FKED" 0402S 917.89,3157 r0 top locked (schematic designator R14)
R15_1 "CRCW040233R2FKED" 0402S 2088,3206 r0 top locked (schematic designator R15)
R15_2 "CRCW040233R2FKED" 0402S 4410.9,3112 r0 top locked (schematic designator R15)
R15_3 "CRCW040233R2FKED" 0402S 3402.9,3206 r0 top locked (schematic designator R15)
R15_4 "CRCW040233R2FKED" 0402S 917.9,3117 r0 top locked (schematic designator R15)
R16_1 "CRCW040210K0FKED" 0402 2704.21,594.52 r90 bottom locked (schematic designator R16)
R16_2 "CRCW040210K0FKED" 0402 3539,586.8 r90 bottom locked (schematic designator R16)
R16_3 "CRCW040210K0FKED" 0402 3993,4546.63 r270 bottom locked (schematic designator R16)
R16_4 "CRCW040210K0FKED" 0402 3067,4522.59 r270 bottom locked (schematic designator R16)
R17_1 "CRCW040210K0FKED" 0402 2745.21,594.52 r90 bottom locked (schematic designator R17)
R17_2 "CRCW040210K0FKED" 0402 3580,586.8 r90 bottom locked (schematic designator R17)
R17_3 "CRCW040210K0FKED" 0402 3952,4546.63 r270 bottom locked (schematic designator R17)
R17_4 "CRCW040210K0FKED" 0402 3026,4522.59 r270 bottom locked (schematic designator R17)
R18_1 "CRCW040210K0FKED" 0402 2786.21,594.52 r90 bottom locked (schematic designator R18)
R18_2 "CRCW040210K0FKED" 0402 3621,586.8 r90 bottom locked (schematic designator R18)
R18_3 "CRCW040210K0FKED" 0402 3911,4546.63 r270 bottom locked (schematic designator R18)
R18_4 "CRCW040210K0FKED" 0402 2985,4522.59 r270 bottom locked (schematic designator R18)
R19 "PMR10EZPJ000" 0805L 1226.16,526.12 r270 bottom locked
R20 "PMR10EZPJ000" 0805L 1226.16,370.14 r270 bottom locked
R21_1 "CRCW04020000Z0ED" 0402 335.85,4877.33 r90 bottom locked (schematic designator R21)
R21_2 "CRCW04020000Z0ED" 0402 5661.15,3686.51 r90 bottom locked (schematic designator R21)
R21_3 "CRCW04020000Z0ED" 0402 5661.15,4377.33 r90 bottom locked (schematic designator R21)
R21_4 "CRCW04020000Z0ED" 0402 335.85,4186.51 r90 bottom locked (schematic designator R21)
R22_1 "CRCW04020000Z0ED" 0402 335.85,4777.33 r90 bottom locked (schematic designator R22)
R22_2 "CRCW04020000Z0ED" 0402 5661.15,3786.51 r90 bottom locked (schematic designator R22)
R22_3 "CRCW04020000Z0ED" 0402 5661.15,4477.33 r90 bottom locked (schematic designator R22)
R22_4 "CRCW04020000Z0ED" 0402 335.85,4086.51 r90 bottom locked (schematic designator R22)
R23_1 "CRCW04020000Z0ED" 0402 335.85,4677.33 r90 bottom locked (schematic designator R23)
R23_2 "CRCW04020000Z0ED" 0402 5661.15,3886.51 r90 bottom locked (schematic designator R23)
R23_3 "CRCW04020000Z0ED" 0402 5661.15,4577.33 r90 bottom locked (schematic designator R23)
R23_4 "CRCW04020000Z0ED" 0402 335.85,3986.51 r90 bottom locked (schematic designator R23)
R24_1 "CRCW04020000Z0ED" 0402 335.85,4577.33 r90 bottom locked (schematic designator R24)
R24_2 "CRCW04020000Z0ED" 0402 5661.15,3986.51 r90 bottom locked (schematic designator R24)
R24_3 "CRCW04020000Z0ED" 0402 5661.15,4677.33 r90 bottom locked (schematic designator R24)
R24_4 "CRCW04020000Z0ED" 0402 335.85,3886.51 r90 bottom locked (schematic designator R24)
R25_1 "CRCW04020000Z0ED" 0402 335.85,4477.33 r90 bottom locked (schematic designator R25)
R25_2 "CRCW04020000Z0ED" 0402 5661.15,4086.51 r90 bottom locked (schematic designator R25)
R25_3 "CRCW04020000Z0ED" 0402 5661.15,4777.33 r90 bottom locked (schematic designator R25)
R25_4 "CRCW04020000Z0ED" 0402 335.85,3786.51 r90 bottom locked (schematic designator R25)
R26_1 "CRCW04020000Z0ED" 0402 335.85,4377.33 r90 bottom locked (schematic designator R26)
R26_2 "CRCW04020000Z0ED" 0402 5661.15,4186.51 r90 bottom locked (schematic designator R26)
R26_3 "CRCW04020000Z0ED" 0402 5661.15,4877.33 r90 bottom locked (schematic designator R26)
R26_4 "CRCW04020000Z0ED" 0402 335.85,3686.51 r90 bottom locked (schematic designator R26)
R27_1 "CRCW040210K0FKED" 0402S 1874.26,2359.18 r180 bottom locked (schematic designator R27)
R27_2 "CRCW040210K0FKED" 0402S 4116.64,2002.51 r270 bottom locked (schematic designator R27)
R27_3 "CRCW040210K0FKED" 0402S 3287.73,3421.24 r90 bottom locked (schematic designator R27)
R27_4 "CRCW040210K0FKED" 0402S 688.22,3895.75 r180 bottom locked (schematic designator R27)
R28_1 "CRCW040210K0FKED" 0402S 2185.91,2178.18 r0 bottom locked (schematic designator R28)
R28_2 "CRCW040210K0FKED" 0402S 4408.64,2117.67 r0 bottom locked (schematic designator R28)
R28_3 "CRCW040210K0FKED" 0402S 3045.36,3289.27 r180 bottom locked (schematic designator R28)
R28_4 "CRCW040210K0FKED" 0402S 839.38,3639.4 r270 bottom locked (schematic designator R28)
R29_1 "CRCW08050000Z0EAHP" 0805_HV 2009.01,2000.95 r270 bottom locked (schematic designator R29)
R29_2 "CRCW08050000Z0EAHP" 0805_HV 4190.26,1997.32 r270 bottom locked (schematic designator R29)
R29_3 "CRCW08050000Z0EAHP" 0805_HV 3218.01,3431.29 r90 bottom locked (schematic designator R29)
R29_4 "CRCW08050000Z0EAHP" 0805_HV 685.87,3799.23 r180 bottom locked (schematic designator R29)
R30_1 "CRCW02010000Z0ED" 0201 2100.55,2349.27 r0 bottom locked (schematic designator R30)
R30_2 "CRCW02010000Z0ED" 0201 4327.2,2313.99 r0 bottom locked (schematic designator R30)
R30_3 "CRCW02010000Z0ED" 0201 3048.83,3156 r0 bottom locked (schematic designator R30)
R30_4 "CRCW02010000Z0ED" 0201 950.89,3648.97 r90 bottom locked (schematic designator R30)
R31_1 "CRCW02010000Z0ED" 0201 1831.26,2193.45 r0 bottom locked (schematic designator R31)
R31_2 "CRCW02010000Z0ED" 0201 4055.83,2158.17 r0 bottom locked (schematic designator R31)
R31_3 "CRCW02010000Z0ED" 0201 3402.09,3239.82 r180 bottom locked (schematic designator R31)
R31_4 "CRCW02010000Z0ED" 0201 850.89,4002.22 r270 bottom locked (schematic designator R31)
R32_1 "CRCW02010000Z0ED" 0201 1844.26,2306.44 r270 bottom locked (schematic designator R32)
R32_2 "CRCW02010000Z0ED" 0201 4068.82,2221.16 r270 bottom locked (schematic designator R32)
R32_3 "CRCW02010000Z0ED" 0201 3393.01,3186.88 r90 bottom locked (schematic designator R32)
R32_4 "CRCW02010000Z0ED" 0201 900.89,4002.22 r270 bottom locked (schematic designator R32)
R33_1 "CRCW02010000Z0ED" 0201 2192.91,2215.45 r180 bottom locked (schematic designator R33)
R33_2 "CRCW02010000Z0ED" 0201 4405.09,2158.17 r180 bottom locked (schematic designator R33)
R33_3 "CRCW02010000Z0ED" 0201 3048.83,3246 r0 bottom locked (schematic designator R33)
R33_4 "CRCW02010000Z0ED" 0201 878.89,3648.97 r90 bottom locked (schematic designator R33)
R34 "CRCW06031R00FKEA" 0603 92.28,1906.59 r90 bottom locked
R35 "PMR10EZPJ000" 0805_HV 414.97,2612.47 r90 bottom locked
R36 "CRCW06031K96FKEA" 0603 92.28,1774.54 r90 bottom locked
R37 "CRCW040210K0FKED" 0402 3512.69,4835.24 r270 top locked
R38 "MCS0402MD1000BE100" 0402 3841.88,4792.82 r180 top locked
R39 "CRCW04023R90JNED" 0402S 781.41,1611.98 r270 bottom locked
R40 "CRCW04023R90JNED" 0402S 385.66,1611.98 r270 bottom locked
R41 "CRCW04023R90JNED" 0402S 781.41,1913.94 r90 bottom locked
R42 "CRCW04023R90JNED" 0402S 385.66,1913.94 r90 bottom locked
R43 "CRCW04020000Z0ED" 0402S 844.21,1445.28 r0 bottom locked
R44 "MCT06030Z0000ZP500" 0603S 215.28,1783.21 r0 bottom locked
R45 "CRCW04020000Z0ED" 0402S 322.87,1445.28 r180 bottom locked
R46 "CRCW04024K70JNED" 0402 964.66,1683.21 r180 bottom locked
R47 "CRCW04024K70JNED" 0402 964.66,1748.23 r0 bottom locked
R48 "CRCW04020000Z0ED" 0402S 844.21,2080.64 r0 bottom locked
R49 "CRCW040210K0FKED" 0402 964.66,1618.2 r0 bottom locked
R50 "CRCW040210K0FKED" 0402 215.19,1826.79 r180 bottom locked
R51 "CRCW040210K0FKED" 0402 215.19,1870.1 r180 bottom locked
R52 "CRCW04020000Z0ED" 0402S 322.87,2080.64 r180 bottom locked
R53 "MCS0402MD1000BE100" 0402 3841.88,4840.22 r180 top locked
R54 "CRCW040210K0FKED" 0402 211.08,1593.92 r180 bottom locked
R55 "CRCW040210K0FKED" 0402 1104.71,1618.2 r180 bottom locked
R56 "CRCW040210K0FKED" 0402 211.08,1637.22 r180 bottom locked
R57 "CRCW040210K0FKED" 0402 964.66,1813.25 r180 bottom locked
R58 "CRCW040210K0FKED" 0402 215.19,1913.4 r0 bottom locked
R59 "CRCW06031R00FKEA" 0603 4978.78,1012.69 r270 bottom locked
R60 "CRCW06031K96FKEA" 0603 4912.9,1012.69 r90 bottom locked
R61 "CRCW040210K0FKED" 0402 3512.69,5068.29 r270 top locked
R62 "MCS0402MD1000BE100" 0402 3841.88,5025.87 r180 top locked
R63 "CRCW04023R90JNED" 0402S 5652.14,824.13 r270 bottom locked
R64 "CRCW04023R90JNED" 0402S 5256.39,824.13 r270 bottom locked
R65 "CRCW04023R90JNED" 0402S 5652.14,1126.09 r90 bottom locked
R66 "CRCW04023R90JNED" 0402S 5256.39,1126.09 r90 bottom locked
R67 "CRCW04020000Z0ED" 0402S 5714.93,657.42 r0 bottom locked
R68 "MCT06030Z0000ZP500" 0603S 5086.01,1000.35 r0 bottom locked
R69 "CRCW04020000Z0ED" 0402S 5193.59,657.42 r180 bottom locked
R70 "CRCW04024K70JNED" 0402 5835.38,895.36 r180 bottom locked
R71 "CRCW04024K70JNED" 0402 5835.38,960.38 r0 bottom locked
R72 "CRCW04020000Z0ED" 0402S 5714.93,1292.79 r0 bottom locked
R73 "MCT06030Z0000ZP500" 0603 1112.58,1868.27 r180 bottom locked
R74 "CRCW040210K0FKED" 0402 5085.91,1043.93 r180 bottom locked
R75 "MCT06030Z0000ZP500" 0603 5946.04,1090.42 r180 bottom locked
R76 "CRCW04020000Z0ED" 0402S 5193.59,1292.79 r180 bottom locked
R77 "MCS0402MD1000BE100" 0402 3841.88,5073.27 r180 top locked
R78 "CRCW040210K0FKED" 0402S 5085.83,811.98 r180 bottom locked
R79 "CRCW040249R9FKED" 0402 4935.79,2752.44 r180 bottom locked
R80 "CRCW040210K0FKED" 0402 5081.8,919.56 r180 bottom locked
R81 "CRCW040210K0FKED" 0402 5835.38,1025.4 r180 bottom locked
R82 "CRCW040249R9FKED" 0402 4871.88,3253.5 r0 bottom locked
R83 "CRCW040249R9FKED" 0402 3910.28,3308.75 r0 bottom locked
R84 "CRCW040249R9FKED" 0402 1454.53,2639.22 r270 bottom locked
R85 "CRCW040249R9FKED" 0402 1360.26,3350.83 r90 bottom locked
R86 "CRCW040210K0FKED" 0402 4434.39,279.21 r270 top locked
R87 "CRCW040210K0FKED" 0402 4292.19,279.21 r270 top locked
R88 "CRCW040210K0FKED" 0402 4740.84,279.21 r270 top locked
R89 "CRCW040210K0FKED" 0402 4598.64,279.21 r270 top locked
R90 "CRCW040210K0FKED" 0402 3841.88,4887.63 r0 top locked
R91 "CRCW040210K0FKED" 0402 3841.88,4745.42 r0 top locked
R92 "CRCW040210K0FKED" 0402 3841.88,5120.67 r0 top locked
R93 "CRCW040210K0FKED" 0402 3841.88,4978.47 r0 top locked
R94 "CRCW040210K0FKED" 0402 964.66,1868.27 r0 bottom locked
R95 "CRCW040210K0FKED" 0402 5835.38,1090.42 r0 bottom locked
R96 "MCT06030Z0000ZP500" 0603 203.2,1687.42 r0 bottom locked
R97 "MCT06030Z0000ZP500" 0603 5073.93,869.37 r0 bottom locked
R98 "CRCW04020000Z0EDHP" 0402S 2084.31,3275.06 r0 bottom locked
R99 "CRCW04020000Z0EDHP" 0402S 1974.65,3335.1 r0 bottom locked
R100 "CRCW04020000Z0EDHP" 0402S 4406.98,3179.22 r0 bottom locked
R101 "CRCW04020000Z0EDHP" 0402S 4291.06,3218 r90 top locked
R102 "CRCW04020000Z0EDHP" 0402S 3448.24,3353.71 r270 bottom locked
R103 "CRCW040243R0JNED" 0402 2934.5,5110.83 r180 top locked
R104 "CRCW040243R0JNED" 0402 2936.49,4744.94 r270 top locked
R105 "ERJ-2RKF1152X" 0402 2837,4913.54 r0 bottom locked
R106 "CRCW040243R0JNED" 0402 3065.57,4939.13 r0 top locked
R107 "ERJ-2GE0R00X" 0402 2588.37,4958.61 r0 top locked
R108 "CRCW040243R0JNED" 0402 2986.58,4744.94 r270 top locked
R109 "ERJ-2GE0R00X" 0402 2588.37,4909.65 r0 top locked
R110 "ERJ-2RKF3091X" 0402 2837,4862.36 r180 bottom locked
R111 "ERJ-2RKF49R9X" 0402 2588.37,4860.7 r0 top locked
R112 "CRCW04020000Z0EDHP" 0402S 3508.27,3437.99 r270 top locked
R113 "CRCW04021K00FKED" 0402 2660.57,4910.51 r90 top locked
R114 "CRCW04020000Z0EDHP" 0402S 933.88,3215.9 r270 bottom locked
R115 "ERJ-2GE0R00X" 0402 2822.43,5161.63 r180 top locked
R116 "ERJ-2GE0R00X" 0402 2763.77,2687.68 r180 top locked
R117 "ERJ-2GE0R00X" 0402 2822.43,5110.83 r180 top locked
R118 "CRCW040210K0FKED" 0402 2805.64,4814.5 r0 top locked
R119 "CRCW040210K0FKED" 0402 2837,4964.72 r0 bottom locked
R120 "CRCW040210K0FKED" 0402 2837,5015.9 r0 bottom locked
R121 "ERJ-2GE0R00X" 0402 2740.15,2608.27 r90 top locked
R122 "ERJ-2GE0R00X" 0402 2672.94,4787 r90 top locked
R123 "ERJ-2GE0R00X" 0402 2725.57,4787 r90 top locked
R124 "CRCW040210K0FKED" 0402 2805.64,4758.04 r180 top locked
R125 "CRCW04020000Z0EDHP" 0402S 781.74,3236.1 r0 bottom locked
R126 "ERJ-2GE0R00X" 0402 4017.56,2749.57 r180 top locked
R127 "CRCW02010000Z0ED" 0201 4047.24,2678.3 r90 top locked
R128 "ERJ-2GE0R00X" 0402 2470.68,2608.27 r270 top locked
R129 "ERJ-2GE0R00X" 0402 4863.64,2678.08 r180 top locked
R130 "ERJ-2GE0R00X" 0402 3776.7,2634.28 r90 top locked
R131 "ERJ-2GE0R00X" 0402 1448.73,2604.99 r180 top locked
R132 "CRCW040243R0JNED" 0402 2106.16,3622.08 r270 bottom locked
R133 "CRCW040243R0JNED" 0402 2155.48,3622.08 r270 bottom locked
R134 "CRCW040243R0JNED" 0402 2382.92,3813.05 r0 bottom locked
R135 "CRCW040243R0JNED" 0402 2081.68,3958.03 r90 bottom locked
R136 "CH02016-100RGFT" 02016 3382.46,3626.25 r0 top locked
R137 "CRCW040210K0FKED" 0402 2056.85,3622.08 r270 bottom locked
